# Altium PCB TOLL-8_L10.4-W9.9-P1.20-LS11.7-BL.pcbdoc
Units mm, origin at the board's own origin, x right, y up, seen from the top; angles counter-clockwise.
Board outline 22.84 x 26.1 mm, 2 copper layers (Top Layer, Bottom Layer), stack 0 mm thick; 1 components, 0 nets, 10 pads, 0 vias.
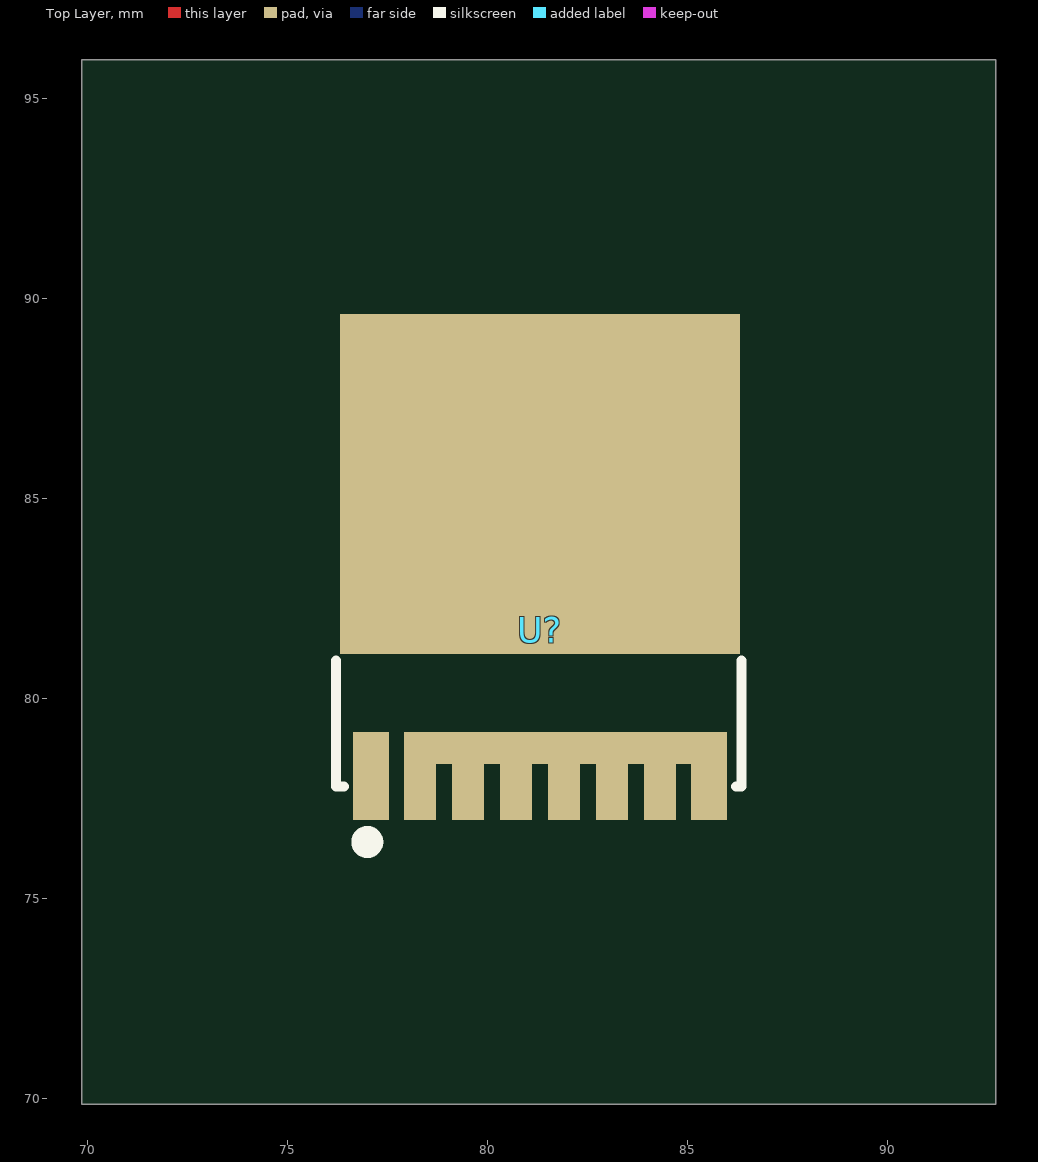
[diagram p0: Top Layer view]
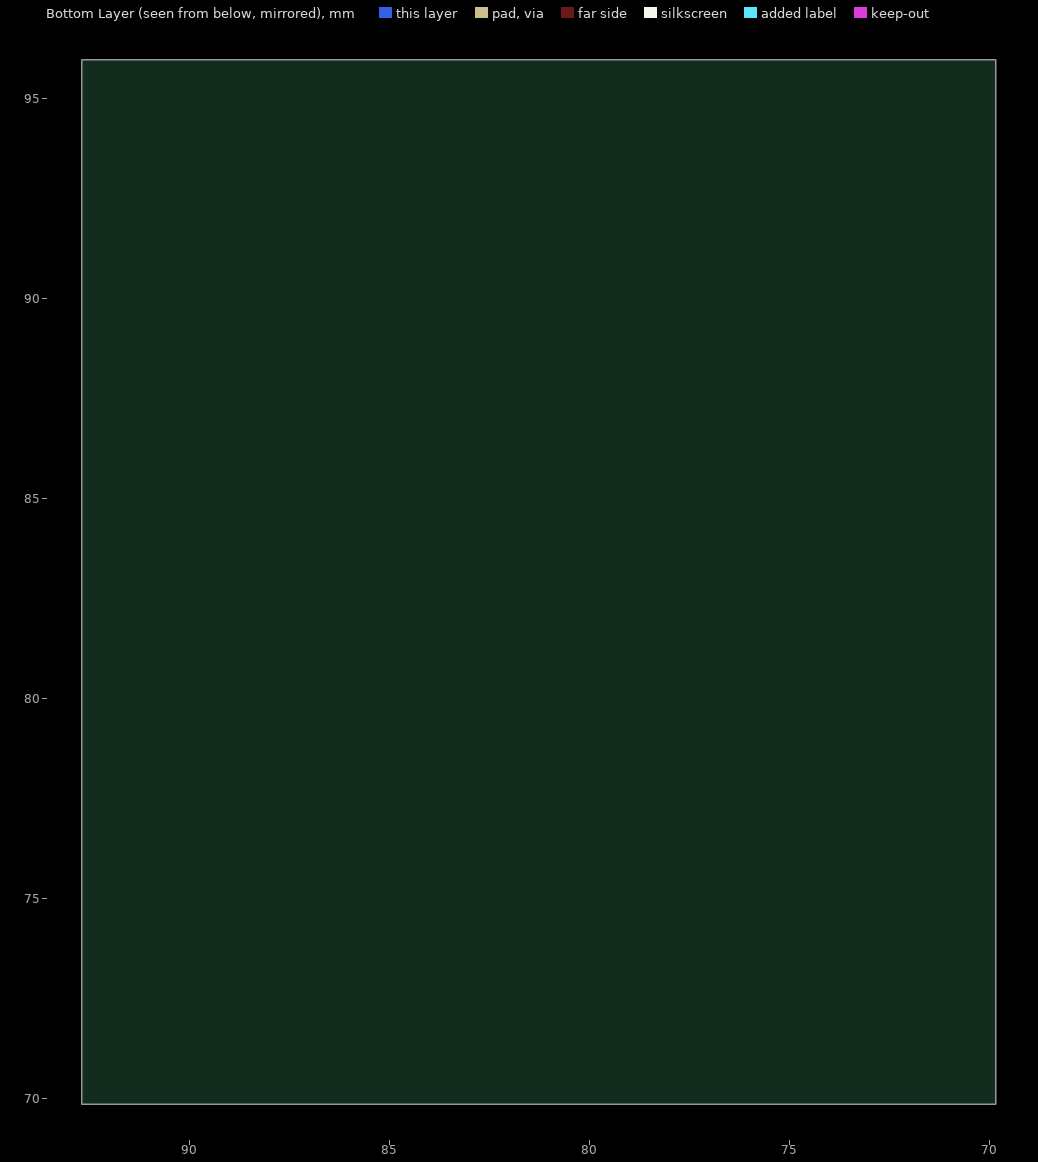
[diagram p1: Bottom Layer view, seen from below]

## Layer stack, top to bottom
Top Layer: signal copper (thickness not stored)
Bottom Layer: signal copper (thickness not stored)

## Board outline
92.69,69.85 69.85,69.85 69.85,95.951 92.69,95.951

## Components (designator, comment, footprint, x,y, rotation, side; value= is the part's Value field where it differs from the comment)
U? "" TOLL-8_L10.4-W9.9-P1.20-LS11.7-BL 81.3,81.701 r0 top

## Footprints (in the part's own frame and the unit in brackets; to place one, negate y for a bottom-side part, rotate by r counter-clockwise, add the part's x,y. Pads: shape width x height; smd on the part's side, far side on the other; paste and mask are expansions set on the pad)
TOLL-8_L10.4-W9.9-P1.20-LS11.7-BL [mm]
  rect 0.9x2.2 smd paste-100 mask+0.05: 1(-4.225,-3.65) 8(4.225,-3.65)
  rect 0.8x2.2 smd paste-100 mask+0.05: 2(-3,-3.65) 3(-1.8,-3.65) 4(-0.6,-3.65) 5(0.6,-3.65) 6(1.8,-3.65) 7(3,-3.65)
  rect 8.08x0.8 smd paste-100 mask+0.05: 8(0.64,-2.95)
  rect 10x8.5 smd paste-100 mask+0.05: 9(0,3.65)
  silkscreen extent -5.1,-5.5 5.04,-0.76

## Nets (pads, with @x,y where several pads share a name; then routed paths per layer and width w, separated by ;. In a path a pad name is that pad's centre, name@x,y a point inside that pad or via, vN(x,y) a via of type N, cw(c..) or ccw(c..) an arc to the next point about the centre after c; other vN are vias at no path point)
pads on no net: U?.1 U?.2 U?.3 U?.4 U?.5 U?.6 U?.7 U?.8 U?.9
